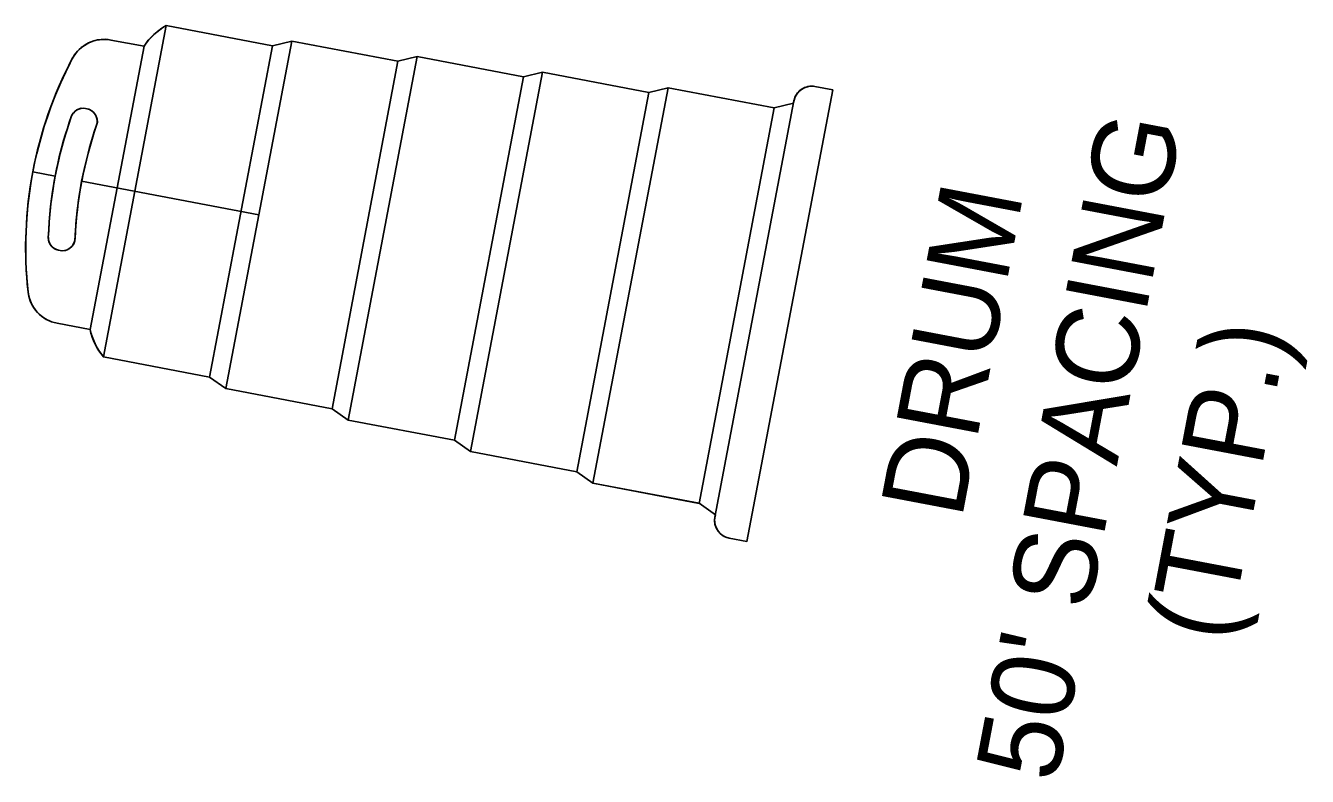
# Model space of a CAD drawing. Extents: x 1615680 to 1619687, y 899305 to 902270.
# Drawn here: x 1619101.4 to 1619194.3, y 901392.1 to 901446.5 of the extents above; entities that cross this region are included whole.
import ezdxf

# ---------------------------------------------------------------- set-up
doc = ezdxf.new("R2010")
doc.units = 0
doc.layers.add('DEV TYPE 3 BARRICADE CELL', color=7, linetype='Continuous')
doc.layers.add('Scratch_Level_5', color=7, linetype='Continuous')

msp = doc.modelspace()

# ---------------------------------------------------------------- linework, layer by layer
at = {"layer": 'Scratch_Level_5'}
for p, q in [((1619107.057, 901422.523), (1619111.615, 901446.526)), ((1619111.615, 901446.526), (1619119.311, 901445.065)), ((1619110.002, 901445.031), (1619107.603, 901445.486)), ((1619115.926, 901420.237), (1619120.705, 901445.403)), ((1619119.311, 901445.065), (1619120.705, 901445.403)), ((1619120.705, 901445.403), (1619128.401, 901443.941)), ((1619106.105, 901424.506), (1619110.002, 901445.031)), ((1619114.754, 901421.062), (1619119.311, 901445.065)), ((1619123.623, 901418.776), (1619128.401, 901443.941)), ((1619124.796, 901417.951), (1619129.794, 901444.279)), ((1619128.401, 901443.941), (1619129.794, 901444.279)), ((1619129.794, 901444.279), (1619137.491, 901442.817)), ((1619132.492, 901416.49), (1619137.491, 901442.817)), ((1619133.665, 901415.665), (1619138.884, 901443.155)), ((1619137.491, 901442.817), (1619138.884, 901443.155)), ((1619138.884, 901443.155), (1619146.581, 901441.693)), ((1619141.362, 901414.204), (1619146.581, 901441.693)), ((1619142.534, 901413.379), (1619147.974, 901442.031)), ((1619146.581, 901441.693), (1619147.974, 901442.031)), ((1619147.974, 901442.031), (1619155.671, 901440.57)), ((1619153.693, 901409.155), (1619159.905, 901441.871)), ((1619159.905, 901441.871), (1619158.623, 901442.115)), ((1619151.371, 901410.925), (1619157.096, 901441.076)), ((1619155.671, 901440.57), (1619157.064, 901440.907)), ((1619105.865, 901440.5), (1619105.757, 901440.521)), ((1619150.231, 901411.918), (1619155.671, 901440.57)), ((1619103.917, 901430.238), (1619103.808, 901430.258)), ((1619106.105, 901424.506), (1619103.706, 901424.961)), ((1619107.057, 901422.523), (1619114.754, 901421.062)), ((1619114.754, 901421.062), (1619115.926, 901420.237)), ((1619115.926, 901420.237), (1619123.623, 901418.776)), ((1619123.623, 901418.776), (1619124.796, 901417.951)), ((1619124.796, 901417.951), (1619132.492, 901416.49)), ((1619132.492, 901416.49), (1619133.665, 901415.665)), ((1619133.665, 901415.665), (1619141.362, 901414.204)), ((1619141.362, 901414.204), (1619142.534, 901413.379)), ((1619142.534, 901413.379), (1619150.231, 901411.918)), ((1619150.24, 901411.923), (1619151.403, 901411.093)), ((1619153.693, 901409.155), (1619152.411, 901409.398))]:
    msp.add_line(p, q, dxfattribs=at)
for points in [[(1619120.705, 901445.403), (1619118.316, 901432.82), (1619105.481, 901435.257), (1619105.699, 901436.334), (1619105.898, 901437.068), (1619106.057, 901437.704), (1619106.227, 901438.242), (1619106.396, 901438.828), (1619106.56, 901439.306), (1619106.618, 901439.539), (1619106.61, 901439.753), (1619106.515, 901440.012), (1619106.362, 901440.225), (1619106.18, 901440.385), (1619105.995, 901440.478), (1619105.757, 901440.521), (1619105.456, 901440.542), (1619105.176, 901440.44), (1619105.012, 901440.336), (1619104.879, 901440.197), (1619104.789, 901440.079), (1619104.724, 901439.927), (1619104.584, 901439.51), (1619104.445, 901439.082), (1619104.315, 901438.653), (1619104.175, 901438.216), (1619104.028, 901437.645), (1619103.862, 901437.03), (1619103.752, 901436.549), (1619103.663, 901436.131), (1619103.564, 901435.622), (1619101.946, 901435.929), (1619102.096, 901436.679), (1619102.236, 901437.261), (1619102.438, 901438.073), (1619102.591, 901438.623), (1619102.775, 901439.235), (1619102.993, 901439.928), (1619103.279, 901440.723), (1619103.582, 901441.506), (1619103.968, 901442.418), (1619104.325, 901443.181), (1619104.643, 901443.835), (1619104.804, 901444.134), (1619104.964, 901444.411), (1619105.178, 901444.67), (1619105.441, 901444.939), (1619105.684, 901445.096), (1619105.989, 901445.279), (1619106.282, 901445.397), (1619106.618, 901445.488), (1619106.906, 901445.53), (1619107.235, 901445.535), (1619107.49, 901445.506), (1619107.603, 901445.486), (1619110.002, 901445.031), (1619110.312, 901445.463), (1619110.507, 901445.677), (1619110.73, 901445.886), (1619110.975, 901446.109), (1619111.3, 901446.347), (1619111.485, 901446.457), (1619111.615, 901446.526), (1619119.311, 901445.065)], [(1619123.623, 901418.776), (1619128.401, 901443.941), (1619129.794, 901444.279), (1619137.491, 901442.817), (1619138.884, 901443.155), (1619133.665, 901415.665), (1619132.492, 901416.49), (1619124.796, 901417.951)], [(1619141.362, 901414.204), (1619146.581, 901441.693), (1619147.974, 901442.031), (1619155.671, 901440.57), (1619157.064, 901440.907), (1619157.128, 901441.228), (1619157.21, 901441.416), (1619157.354, 901441.638), (1619157.531, 901441.836), (1619157.69, 901441.945), (1619157.904, 901442.052), (1619158.148, 901442.117), (1619158.336, 901442.136), (1619158.504, 901442.141), (1619158.623, 901442.115), (1619159.905, 901441.871), (1619153.693, 901409.155), (1619152.411, 901409.398), (1619152.231, 901409.444), (1619152.034, 901409.528), (1619151.862, 901409.644), (1619151.72, 901409.772), (1619151.614, 901409.894), (1619151.478, 901410.105), (1619151.401, 901410.332), (1619151.354, 901410.572), (1619151.344, 901410.713), (1619151.371, 901410.925), (1619151.403, 901411.093), (1619150.24, 901411.923), (1619142.534, 901413.379)], [(1619115.926, 901420.237), (1619118.316, 901432.82), (1619105.481, 901435.257), (1619105.363, 901434.634), (1619105.298, 901434.15), (1619105.225, 901433.668), (1619105.164, 901433.146), (1619105.103, 901432.577), (1619105.058, 901431.995), (1619105.013, 901431.367), (1619104.989, 901430.941), (1619104.91, 901430.721), (1619104.781, 901430.54), (1619104.601, 901430.377), (1619104.425, 901430.289), (1619104.227, 901430.233), (1619104.047, 901430.22), (1619103.694, 901430.287), (1619103.513, 901430.369), (1619103.318, 901430.527), (1619103.177, 901430.723), (1619103.077, 901430.985), (1619103.065, 901431.189), (1619103.094, 901431.665), (1619103.131, 901432.305), (1619103.25, 901433.621), (1619103.38, 901434.552), (1619103.494, 901435.251), (1619103.564, 901435.622), (1619101.946, 901435.929), (1619101.819, 901435.26), (1619101.691, 901434.386), (1619101.579, 901433.498), (1619101.501, 901432.549), (1619101.45, 901431.64), (1619101.421, 901430.644), (1619101.437, 901429.498), (1619101.467, 901428.818), (1619101.548, 901427.717), (1619101.597, 901427.245), (1619101.644, 901426.94), (1619101.749, 901426.602), (1619101.893, 901426.275), (1619102.158, 901425.897), (1619102.413, 901425.614), (1619102.673, 901425.405), (1619102.975, 901425.217), (1619103.285, 901425.074), (1619103.706, 901424.961), (1619106.105, 901424.506), (1619106.155, 901424.257), (1619106.237, 901423.998), (1619106.375, 901423.644), (1619106.543, 901423.294), (1619106.719, 901422.989), (1619107.057, 901422.523), (1619114.754, 901421.062)]]:
    msp.add_lwpolyline(points, close=True, dxfattribs=at)
for centre, radius, start, end in [((1619113.785, 901442.569), 4.514, 118.73583, 146.94336), ((1619107.116, 901442.921), 2.611, 79.24937, 152.30015), ((1619130.909, 901430.429), 29.485, 152.30015, 186.19859), ((1619158.379, 901440.832), 1.306, 79.24937, 169.24937), ((1619132.531, 901430.121), 29.485, 160.57536, 177.92338), ((1619105.586, 901439.623), 0.914, 79.24937, 160.57536), ((1619105.695, 901439.602), 0.914, 341.10062, 79.24937), ((1619134.455, 901429.756), 29.485, 161.10062, 177.39812), ((1619103.979, 901431.156), 0.914, 177.92338, 259.24937), ((1619104.087, 901431.136), 0.914, 259.24937, 357.39812), ((1619104.193, 901427.527), 2.611, 186.19859, 259.24937), ((1619110.527, 901425.41), 4.514, 191.55539, 219.76292), ((1619152.654, 901410.681), 1.306, 169.24937, 259.24937)]:
    msp.add_arc(centre, radius, start, end, dxfattribs=at)

# ---------------------------------------------------------------- texts
at = {"layer": 'DEV TYPE 3 BARRICADE CELL'}
for s, p in [("50' SPACING", (1619176.132, 901391.581)), ('DRUM', (1619169.248, 901410.686)), ('(TYP.)', (1619188.57, 901401.725))]:
    msp.add_text(s, height=6, rotation=79.24937, dxfattribs=at).set_placement(p)

doc.saveas('drawing.dxf')
